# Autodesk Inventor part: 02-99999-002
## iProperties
Manager: Boekels
Company: Test
Created: 2005-01
Part Number: 02-99999-002
Project: 99999
User Status: Wird geändert
Description: Würfel
Document SubType Name: Modeling
Designer: Boekels
Engineer: Boekels
Manufacturer: Standard
Standards Organization: Custom
Masse: 224,4 g
Volumen: 224,4E+3 mm^3
Flaeche: 744,1E+2 mm^2
Title: Würfel
Author: Boekels
Revision Number: 1
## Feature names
1. Extrusion1
2. Drehung2 [Revolution]
3. Spiegeln1 [Mirror]
4. Spiegeln2 [Mirror]
